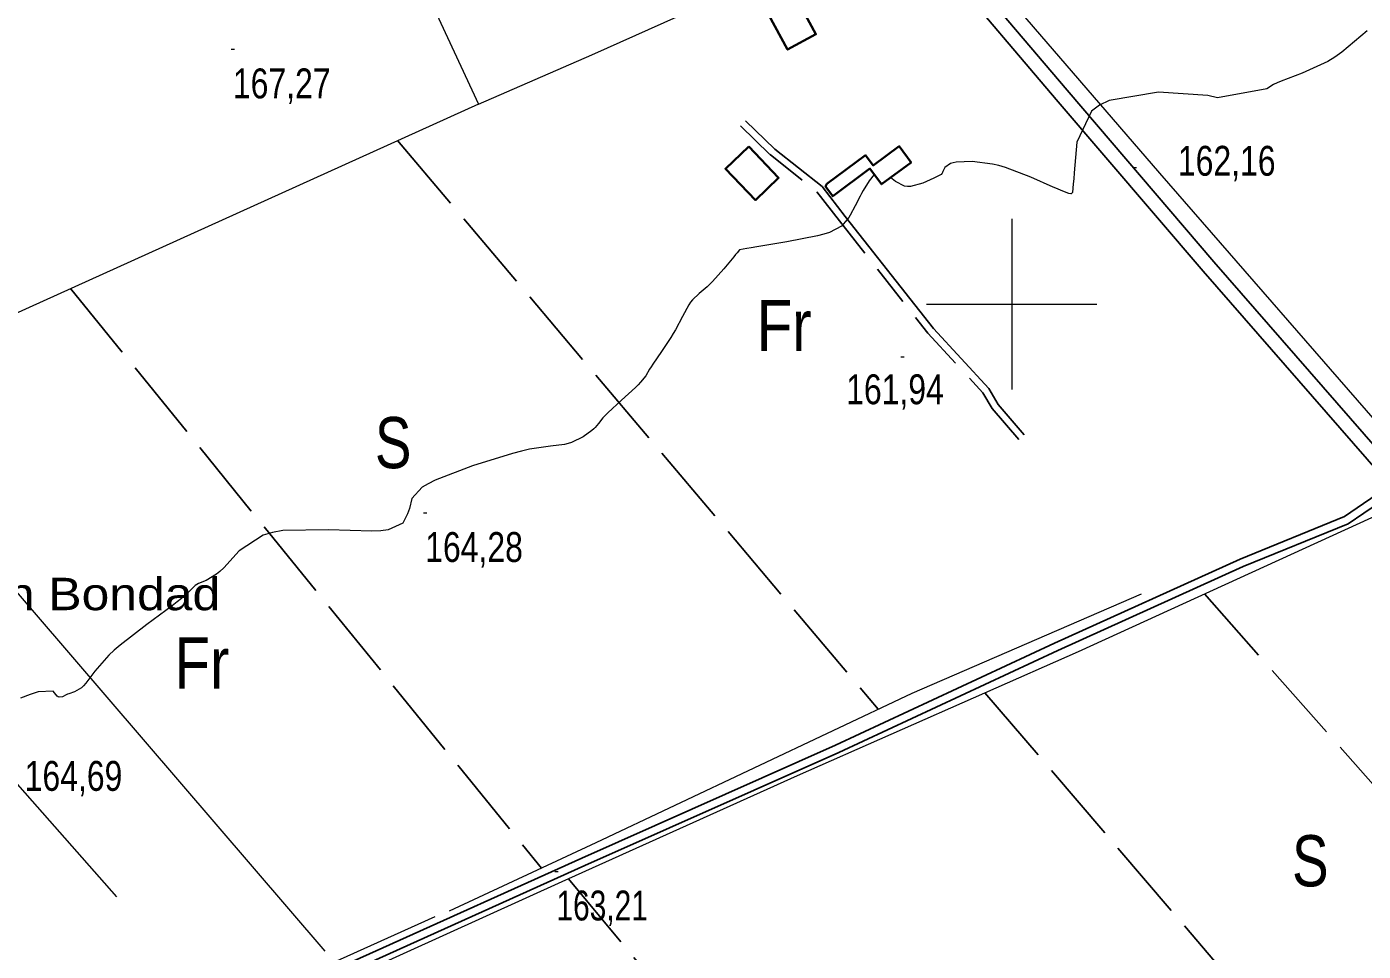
# Model space of a CAD drawing. Extents: x -807245 to 6129983, y -54972206 to 262146364.
# Drawn here: x 490211.3 to 490603.1, y 4382310.4 to 4382581.3 of the extents above; entities that cross this region are included whole.
import ezdxf
from ezdxf.enums import TextEntityAlignment as Align

# ---------------------------------------------------------------- set-up
doc = ezdxf.new("R2010")
doc.units = 0
doc.header["$LTSCALE"] = 4
doc.linetypes.add('LONG_DASHED', pattern=[7.5, 6, -1.5])
doc.linetypes.add('MEDIUM_DASHED', pattern=[4.5, 3, -1.5])
for name, color, linetype, lineweight in [('1', 7, 'Continuous', 13), ('25', 7, 'LONG_DASHED', 25), ('27', 7, 'Continuous', 25), ('36', 7, 'Continuous', 25), ('38', 7, 'Continuous', 25), ('39', 7, 'Continuous', 13), ('47', 7, 'Continuous', 35), ('51', 7, 'Continuous', 13), ('7', 7, 'Continuous', 13), ('9', 7, 'Continuous', 13)]:
    doc.layers.add(name, color=color, linetype=linetype, lineweight=lineweight)
doc.layers.add('31', color=7, linetype='Continuous')
doc.layers.add('5', color=7, linetype='Continuous')

msp = doc.modelspace()

# ---------------------------------------------------------------- linework, layer by layer
at = {"layer": '1'}
for p, q in [((490500, 4382525), (490500, 4382475)), ((490475, 4382500), (490525, 4382500))]:
    msp.add_line(p, q, dxfattribs=at)
at = {"layer": '25'}
for p, q in [((490320.01, 4382547.94), (490460.91, 4382381.29)), ((490224.15, 4382504.59), (490362.13, 4382334.75)), ((490556.49, 4382415.1), (490700.7, 4382252.08)), ((490492.13, 4382386.15), (490634.85, 4382219.51)), ((490370.1, 4382331.65), (490509.6, 4382163.37))]:
    msp.add_line(p, q, dxfattribs=at)
at = {"layer": '27'}
msp.add_spline([(491255.21, 4383970.03), (491244.34, 4383967.52), (491230.36, 4383957.66), (491230.81, 4383957.81), (491230.81, 4383957.81), (491220.15, 4383951.47), (491212.7, 4383943.01), (491205.06, 4383944.23), (491184.85, 4383957.71), (491152.82, 4383981.27), (491128.36, 4384004.58), (491128.29, 4384004.88), (491122.26, 4384021.39), (491095.75, 4384034.59), (491071.07, 4384059.32), (491064.71, 4384065.12)], degree=3, dxfattribs=at)
at = {"layer": '36'}
for points in [[(490398.49, 4382722.41), (490395.81, 4382712.75), (490395.43, 4382709.44), (490395.43, 4382707.9), (490396.37, 4382706.26), (490407.84, 4382692.16), (490424.97, 4382670.86), (490449.74, 4382641.51), (490483.7, 4382601.01), (490516.25, 4382562.67), (490559.26, 4382512.41), (490615.33, 4382448.1), (490646.64, 4382411.97), (490693.16, 4382359.3), (490728.4, 4382319.2)], [(490391.36, 4382710.01), (490392.25, 4382704.84), (490404.57, 4382689.58), (490421.76, 4382668.21), (490446.56, 4382638.83), (490480.52, 4382598.33), (490513.08, 4382559.97), (490556.11, 4382509.69), (490612.19, 4382445.37), (490643.51, 4382409.23), (490690.04, 4382356.55), (490725.27, 4382316.45)]]:
    msp.add_lwpolyline(points, dxfattribs=at)
at = {"layer": '38'}
for points in [[(490421.95, 4382553.77), (490430.6, 4382545.41), (490444.42, 4382534.46), (490451.21, 4382525.69), (490477.05, 4382492.88), (490493.26, 4382475.31), (490495.99, 4382470.64), (490503.69, 4382461.74)], [(490014.94, 4382172.34), (490069.13, 4382197.01), (490119.32, 4382220.08), (490156.59, 4382236.95), (490208.05, 4382260.42), (490272.29, 4382289.27), (490314.7, 4382308.35), (490374.92, 4382335.55), (490449.29, 4382368.61), (490513.5, 4382398.52), (490567.89, 4382423.09), (490598.63, 4382435.68), (490612.38, 4382445.04)], [(490116.6, 4382221.43), (490118.34, 4382222.22), (490155.62, 4382239.09), (490207.08, 4382262.57), (490271.32, 4382291.42), (490313.73, 4382310.5), (490373.96, 4382337.7), (490448.31, 4382370.75), (490512.52, 4382400.66), (490566.96, 4382425.25), (490597.51, 4382437.77), (490610.86, 4382446.86)]]:
    msp.add_lwpolyline(points, dxfattribs=at)
at = {"layer": '38', "linetype": 'MEDIUM_DASHED'}
msp.add_lwpolyline([(490420.48, 4382552.25), (490429.21, 4382543.82), (490442.91, 4382532.96), (490449.55, 4382524.39), (490475.44, 4382491.51), (490491.55, 4382474.05), (490494.27, 4382469.41), (490502.09, 4382460.36)], dxfattribs=at)
at = {"layer": '39'}
msp.add_spline([(489117.55, 4382698.88), (489119.92, 4382672.68), (489122.01, 4382625.33), (489125.29, 4382585.13), (489126.65, 4382547.13), (489128.77, 4382508.18), (489130.39, 4382475.59), (489130.93, 4382447.55), (489133.21, 4382401.71), (489136.74, 4382363.61), (489144.72, 4382321.33), (489154.17, 4382280.07), (489166.23, 4382246.73), (489180.75, 4382210.53), (489205.22, 4382168.24), (489224.8, 4382133.94), (489257.72, 4382093.12), (489296.35, 4382054.96), (489327.82, 4382028.88), (489364.04, 4382002), (489408.28, 4381978.37), (489453.5, 4381958.06), (489487.73, 4381946.36), (489523.65, 4381936.12), (489563.73, 4381928.23), (489620.66, 4381920.7), (489680.32, 4381912.26), (489735.44, 4381905.59), (489799.91, 4381896.95), (489865.43, 4381887.81), (489926.74, 4381879.18), (489976.6, 4381873.08), (490039.39, 4381865.3), (490107.84, 4381856.38), (490175.25, 4381846.83), (490254.89, 4381836.5), (490348.33, 4381823.47), (490406.14, 4381813.57), (490409.06, 4381812.73)], degree=3, dxfattribs=at)
at = {"layer": '47'}
for points in [[(490426.89, 4382588.3), (490434.31, 4382574.59), (490442.63, 4382579.1), (490438.91, 4382585.96), (490437.62, 4382585.27), (490435.39, 4382589.41), (490440.64, 4382592.25), (490438.04, 4382597.05), (490428.58, 4382591.93), (490429.51, 4382590.2), (490426.95, 4382588.82)], [(490422.94, 4382546.21), (490431.69, 4382537.02), (490424.86, 4382530.51), (490416.11, 4382539.7)], [(490445.83, 4382535.24), (490457.19, 4382543.67), (490459.42, 4382540.65), (490467.03, 4382546.27), (490470.5, 4382541.56), (490461.82, 4382535.16), (490458.44, 4382539.72), (490447.55, 4382531.65), (490445.41, 4382534.52)]]:
    msp.add_lwpolyline(points, close=True, dxfattribs=at)
at = {"layer": '51'}
for p, q in [((490343.69, 4382558.65), (490197.98, 4382492.74)), ((490170.37, 4382459.61), (490298.66, 4382310.4)), ((490144.4, 4382431.8), (490237.64, 4382326.31))]:
    msp.add_line(p, q, dxfattribs=at)
for points in [[(490290.56, 4382672.99), (490343.69, 4382558.65), (490376.9, 4382573.03), (490464.61, 4382612.38), (490425.63, 4382659.3)], [(490482.83, 4382608.57), (490543.35, 4382538.37), (490613.76, 4382457.5)], [(490277.36, 4382289.61), (490368.26, 4382330.82), (490437.18, 4382361.88), (490519.55, 4382398.26), (490605.61, 4382437.5), (490613.34, 4382441.12)], [(490537.93, 4382415.01), (490470.77, 4382385.94), (490378.13, 4382342.21), (490335.15, 4382322.15)], [(490330.91, 4382320.48), (490270.46, 4382293.21), (490186.91, 4382255.45), (490119.12, 4382224.49)]]:
    msp.add_lwpolyline(points, dxfattribs=at)
at = {"layer": '7'}
for p, q in [((490271.22, 4382574.7), (490272.22, 4382574.7)), ((490535.54, 4382540.09), (490536.54, 4382540.09)), ((490467.5, 4382484.56), (490468.5, 4382484.56)), ((490327.59, 4382438.84), (490328.59, 4382438.84)), ((490366.04, 4382333.79), (490367.04, 4382333.79))]:
    msp.add_line(p, q, dxfattribs=at)
at = {"layer": '9'}
for points in [[(490604.24, 4382580.12), (490596.79, 4382573.83), (490594.72, 4382572.41), (490592.65, 4382571.13)], [(490592.65, 4382571.13), (490585.18, 4382567.66), (490579.03, 4382565.4), (490577.8, 4382564.88), (490576.77, 4382564.41), (490574.76, 4382563.07), (490560.36, 4382560.46), (490557.54, 4382561.19), (490543.08, 4382562.17), (490528.58, 4382559.72), (490525.73, 4382558.29), (490523.39, 4382556.54), (490519.13, 4382547.51), (490518.34, 4382538.46), (490518.18, 4382536.7), (490518.05, 4382535.25), (490517.78, 4382532.72), (490517.56, 4382532.41), (490517.46, 4382532.36), (490517.33, 4382532.34), (490516.71, 4382532.43), (490514.55, 4382533.29), (490513.45, 4382533.76), (490512.14, 4382534.33), (490505.62, 4382537.22), (490498.15, 4382540.08), (490496.25, 4382540.63), (490494.41, 4382541.08), (490488.37, 4382541.82), (490483.76, 4382541.59), (490482.82, 4382541.42), (490482.04, 4382541.2), (490480.43, 4382540.06), (490479.86, 4382538.87), (490479.73, 4382538.62), (490479.62, 4382538.42), (490479.28, 4382537.99), (490478.31, 4382537.49), (490477.78, 4382537.25), (490477.15, 4382536.95), (490473.96, 4382535.48), (490470.35, 4382534.47), (490469.45, 4382534.46), (490468.6, 4382534.57), (490465.91, 4382535.93), (490464.5, 4382537.14)], [(490459.68, 4382538.05), (490458.22, 4382536.14), (490456.43, 4382533.27), (490455.97, 4382532.47), (490455.54, 4382531.67), (490454.09, 4382528.79), (490452.67, 4382526.12), (490452.24, 4382525.45), (490451.81, 4382524.82), (490450.13, 4382522.82), (490446.59, 4382521.02), (490444.98, 4382520.53), (490443.1, 4382520.03), (490434.05, 4382518.23), (490425.34, 4382516.78), (490423.68, 4382516.5), (490422.34, 4382516.28), (490420.23, 4382515.93), (490420.23, 4382515.93), (490420.23, 4382515.93), (490420.23, 4382515.93), (490420.23, 4382515.93), (490419.51, 4382515.08), (490419.06, 4382514.54), (490418.51, 4382513.87)], [(490418.51, 4382513.87), (490415.58, 4382510.38), (490412.26, 4382506.62), (490411.45, 4382505.79), (490410.7, 4382505.05), (490408.37, 4382503.1), (490406.4, 4382501.25), (490405.86, 4382500.56), (490405.33, 4382499.8), (490403.46, 4382496.43), (490401.41, 4382492.49), (490400.76, 4382491.38), (490400.08, 4382490.26), (490397.36, 4382486.11), (490394.86, 4382482.47), (490394.33, 4382481.66), (490393.86, 4382480.93), (490392.74, 4382479.04), (490391.24, 4382477.12), (490390.54, 4382476.38), (490389.71, 4382475.56), (490385.65, 4382471.83), (490381.65, 4382468.17), (490380.85, 4382467.39), (490380.18, 4382466.71), (490378.89, 4382465.07), (490377.94, 4382463.88), (490377.49, 4382463.47), (490376.95, 4382463.03), (490374.35, 4382461.16), (490370.97, 4382459.46), (490369.95, 4382459.14), (490368.89, 4382458.87), (490364.78, 4382458.41), (490358.64, 4382457.48), (490356.3, 4382456.91), (490353.7, 4382456.22), (490341.99, 4382452.6), (490331.05, 4382448.42), (490328.92, 4382447.36), (490327.18, 4382446.35), (490324.16, 4382443.06), (490323.47, 4382440.12), (490323.2, 4382439.33), (490322.89, 4382438.55), (490321.51, 4382435.79), (490317.19, 4382433.86), (490315.04, 4382433.6), (490312.46, 4382433.45), (490299.72, 4382433.89), (490286.31, 4382433.67), (490283.31, 4382433.11), (490280.64, 4382432.34), (490273.57, 4382427.73), (490269.03, 4382422.74), (490267.94, 4382421.72), (490266.93, 4382420.86), (490263.89, 4382419.07), (490261.63, 4382418.17), (490261.11, 4382417.87), (490260.64, 4382417.55), (490259.3, 4382416.21), (490256.7, 4382413.76), (490255.43, 4382412.74), (490253.92, 4382411.58), (490246.46, 4382406.12), (490238.65, 4382400.12), (490236.91, 4382398.6), (490235.35, 4382397.15), (490231.28, 4382392.46), (490228.61, 4382388.92), (490227.94, 4382388.2), (490227.3, 4382387.6), (490225.26, 4382386.37), (490223.59, 4382385.86), (490223.2, 4382385.71), (490222.83, 4382385.55), (490221.74, 4382384.95), (490220.77, 4382384.81), (490220.48, 4382384.95), (490220.19, 4382385.17), (490219.05, 4382386.59), (490214.67, 4382386.42), (490212.33, 4382385.62), (490209.5, 4382384.51)]]:
    msp.add_lwpolyline(points, dxfattribs=at)

# ---------------------------------------------------------------- texts
at = {"layer": '31'}
for s, width, p in [('Fr', 0.85, (490433.29, 4382486.27)), ('S', 0.8, (490318.7, 4382451.94)), ('Fr', 0.85, (490262.66, 4382387.36)), ('S', 0.8, (490587.53, 4382329.41))]:
    msp.add_text(s, height=15, dxfattribs=dict(at, width=width)).set_placement(p, align=Align.CENTER)
at = {"layer": '5', "width": 1.15}
msp.add_text("Caseta d'en Bondad", height=9.5, dxfattribs=at).set_placement((490136.06, 4382410.33))
at = {"layer": '7'}
for s, width, p in [('167,27', 0.8, (490271.72, 4382560.33)), ('162,16', 0.8, (490548.72, 4382537.65)), ('161,94', 0.8, (490451.48, 4382470.69)), ('164,28', 0.8, (490328.09, 4382424.47)), ('164,69', 0.8, (490210.69, 4382357.4)), ('163,21', 0.75, (490366.54, 4382319.42))]:
    msp.add_text(s, height=8.75, dxfattribs=dict(at, width=width)).set_placement(p)

doc.saveas('drawing.dxf')
